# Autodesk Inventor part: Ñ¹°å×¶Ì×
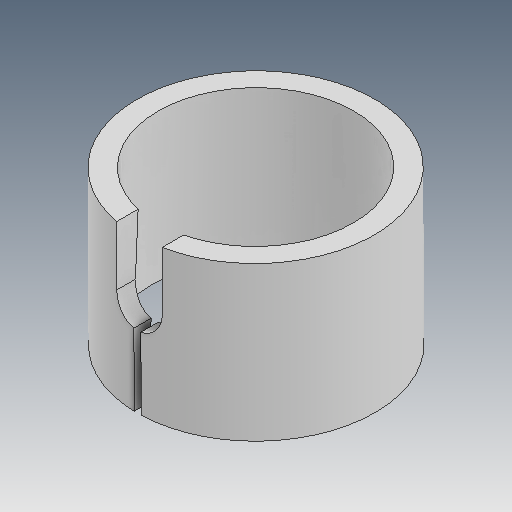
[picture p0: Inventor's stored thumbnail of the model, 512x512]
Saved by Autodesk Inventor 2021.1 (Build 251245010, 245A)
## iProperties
Created: 2019-04
Part Number: Ñ¹°å×¶Ì×
Material: Ogólny
Document SubType Name: Modeling
Designer: user
Density: 1 g/cm^3
Appearance: Domyślna
Author: user
Revision Number: ÈÎºÎ
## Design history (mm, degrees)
feature "ÇÐ³ý-À­Éì1"
node "Bryła1"
